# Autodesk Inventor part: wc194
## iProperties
Shininess: 64.0
Length Units: 11272
Angle Units: 11279
Time Units: 11290
Mass Units: 11286
Length Display Precision: 3
Angle Display Precision: 2
Compacted: True
Part Number: wc194
Document SubType Name: Modeling
Created: 2004-08
Designer: John Blackburn
Manufacturer: Standard
Standards Organization: Custom
Density: 0.0
Volumn: 0.0
Area: 0.0
PropertySet Name: Model Information
Control State: 0
Master: False
Checked Out: False
Author: John Blackburn
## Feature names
1. Base1
